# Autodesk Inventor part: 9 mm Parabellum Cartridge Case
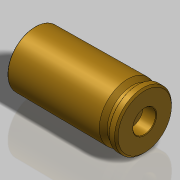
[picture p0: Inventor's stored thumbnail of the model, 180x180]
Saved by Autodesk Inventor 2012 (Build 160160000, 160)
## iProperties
Company: MH Vaaben Teknik
Category: Sten MK II Magazine
Created: 2011-12
Part Number: 9 mm Parabellum Cartridge Case
Material: Brass, Soft Yellow
Document SubType Name: Modeling
Designer: Michael Høgh
Density: 8.47 g/cm^3
Mass: 2.81266 g
Surface Area: 12.4131 cm^2
Volume: 0.332073 cm^3
Project: Sten MK II
Engineer: MH Vaaben Teknik
Author: Michael Høgh
Title: 9 mm Parabellum Cartridge Case
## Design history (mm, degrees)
sketch "Sketch1"
  geometry: L1 (18.592, 0)-(18.592, 4.98) reference; L2 (18.592, 4.98)-(17.322, 4.98); L3 (17.322, 4.98)-(17.322, 4.395); L4 (17.322, 4.395)-(16.422, 4.395); L5 (16.422, 4.395)-(15.608, 4.965); L6 (15.608, 4.965)-(-0.558, 4.825); L7 (-0.558, 4.825)-(-0.558, 0); L8 (-27.844, 0)-(26.647, 0) reference; 1 further point
  constraints: 16 end point, 3 parallel, 2 perpendicular, 2 point on line, 2 vertical, 1 horizontal
  dimensions: "d0" = 4.98 distance between parallel lines of L2 L8; "d1" = 1.27 distance between parallel lines of L1 L3; "d2" = 4.395 distance between parallel lines of L8 L4; "d3" = 35 deg angle of L5 L4; "d4" = 4.965 distance from line of L8 L5.end; "d5" = 19.15 distance between parallel lines of L1 L7; "d6" = 4.825 distance from line of L6.end L8; "d11" = 0.9 distance of L3.end L4.end
revolve "Revolution1" sketch "Sketch1" stored, may be unused: angle "d7" = 90 deg
chamfer "Chamfer1" distance "d8" = 0.3; stored, may be unused: second distance "d9" = 2, angle "d10" = 45 deg
sketch "Sketch2"
  geometry: C1 r 4.825 at (0, 0) reference; C2 r 4.515 at (0, 0)
  constraints: 1 centre point, 1 coincident
  dimensions: "d12" = 9.03 diameter of C2
extrude "Extrusion1" cut sketch "Sketch2" distance "d13" = 16.15; taper "d14" = 0.5 deg
fillet "Fillet1" dims "d15" = 0.7
fillet "Fillet2" dims "d16" = 0.05
chamfer "Chamfer2" distance "d17" = 0.05; stored, may be unused: second distance "d18" = 2, angle "d19" = 45 deg
sketch "Sketch3"
  geometry: C1 r 4.68 at (0, 0) reference; C2 r 2 at (0, 0)
  constraints: 1 centre point, 1 coincident
  dimensions: "d20" = 4 diameter of C2
extrude "Extrusion2" cut sketch "Sketch3" distance "d21" = 2.3; taper "d22" = 0 deg
chamfer "Chamfer3" distance "d23" = 0.1; stored, may be unused: second distance "d24" = 2, angle "d25" = 45 deg
sketch "Sketch4"
  geometry: C1 r 2 at (0, 0) reference; C2 r 0.25 at (-1, 0); C3 r 0.25 at (1, 0)
  constraints: 2 centre point
  dimensions: "d26" = 0.5 diameter of C2; "d27" = 0.5 diameter of C3; "d28" = 1 distance of C1.centre C2.centre; "d29" = 1 distance of C3.centre C1.centre
extrude "Extrusion3" cut sketch "Sketch4" stored distance "d30" = 2.3; taper "d31" = 0 deg
body "Solid1"
